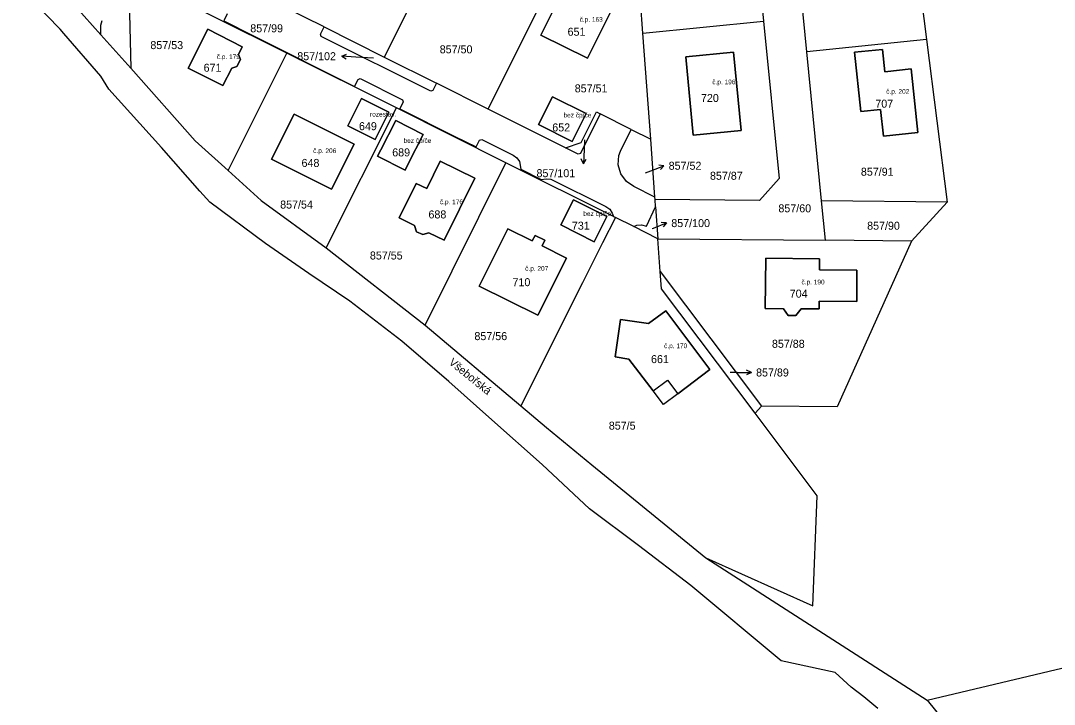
# Model space of a CAD drawing. Extents: x -887272 to -877616, y -1026687 to -1019819.
# Drawn here: x -886371.5 to -886152, y -1024532.4 to -1024387 of the extents above; entities that cross this region are included whole.
import ezdxf

# ---------------------------------------------------------------- set-up
doc = ezdxf.new("R2010")
doc.units = 0
for name, color, linetype in [('Definiční body', 7, 'Continuous'), ('Hranice parcel', 7, 'Continuous'), ('Parcelní čísla', 7, 'Continuous'), ('Polygon budovy', 7, 'Continuous'), ('Pop  PČ popisy', 7, 'Continuous'), ('Vnitřní kresba', 7, 'Continuous')]:
    doc.layers.add(name, color=color, linetype=linetype)

msp = doc.modelspace()

# ---------------------------------------------------------------- linework, layer by layer
at = {"layer": 'Hranice parcel'}
for p, q in [((-886183.54, -1024356.31), (-886179.13, -1024391.05)), ((-886204.52, -1024393.61), (-886207.95, -1024358.74)), ((-886278.64, -1024363.46), (-886294.28, -1024394.77)), ((-886272.23, -1024405.8), (-886256.6, -1024374.49)), ((-886365.01, -1024378.17), (-886354.46, -1024390.01)), ((-886307.08, -1024388.36), (-886319.32, -1024382.23)), ((-886239.34, -1024389.68), (-886239.83, -1024382.88)), ((-886239.34, -1024389.68), (-886213.7, -1024387.12)), ((-886307.08, -1024388.36), (-886294.28, -1024394.77)), ((-886354.51, -1024398.78), (-886362.33, -1024389.78)), ((-886354.46, -1024390.01), (-886348.15, -1024397.1)), ((-886237.7, -1024412.2), (-886239.34, -1024389.68)), ((-886179.13, -1024391.05), (-886204.52, -1024393.61)), ((-886179.13, -1024391.05), (-886174.74, -1024425.59)), ((-886201.39, -1024425.35), (-886204.52, -1024393.61)), ((-886327.47, -1024418.9), (-886314.97, -1024393.92)), ((-886291.71, -1024405.57), (-886314.97, -1024393.92)), ((-886294.28, -1024394.77), (-886283.2, -1024400.31)), ((-886352.76, -1024401.6), (-886354.51, -1024398.78)), ((-886272.23, -1024405.8), (-886283.2, -1024400.31)), ((-886341.64, -1024413.97), (-886352.76, -1024401.6)), ((-886306.62, -1024435.3), (-886291.71, -1024405.57)), ((-886268.45, -1024417.21), (-886291.71, -1024405.57)), ((-886255.82, -1024414.02), (-886272.23, -1024405.8)), ((-886241.84, -1024410.12), (-886248.41, -1024406.82)), ((-886241.84, -1024410.12), (-886237.7, -1024412.2)), ((-886236.81, -1024424.51), (-886237.7, -1024412.2)), ((-886333.44, -1024423.24), (-886341.64, -1024413.97)), ((-886285.57, -1024451.74), (-886268.45, -1024417.21)), ((-886245.62, -1024428.63), (-886268.45, -1024417.21)), ((-886236.77, -1024425.07), (-886236.81, -1024424.51)), ((-886236.66, -1024426.62), (-886236.77, -1024425.07)), ((-886236.66, -1024426.62), (-886236.17, -1024433.37)), ((-886174.74, -1024425.59), (-886201.39, -1024425.35)), ((-886200.57, -1024433.71), (-886201.39, -1024425.35)), ((-886174.74, -1024425.59), (-886182.28, -1024433.89)), ((-886245.62, -1024428.63), (-886245.19, -1024428.85)), ((-886241.27, -1024430.81), (-886245.19, -1024428.85)), ((-886236.17, -1024433.37), (-886241.27, -1024430.81)), ((-886310.31, -1024440.75), (-886319.49, -1024434.41)), ((-886306.62, -1024435.3), (-886285.57, -1024451.74)), ((-886235.67, -1024440.34), (-886236.17, -1024433.37)), ((-886236.17, -1024433.37), (-886200.57, -1024433.71)), ((-886182.28, -1024433.89), (-886200.57, -1024433.71)), ((-886301.62, -1024446.68), (-886310.31, -1024440.75)), ((-886235.67, -1024440.34), (-886214.13, -1024468.94)), ((-886290.56, -1024455.12), (-886301.62, -1024446.68)), ((-886285.57, -1024451.74), (-886265.29, -1024468.92)), ((-886280.6, -1024463.7), (-886290.56, -1024455.12)), ((-886271.41, -1024471.88), (-886280.6, -1024463.7)), ((-886214.13, -1024468.94), (-886215.5, -1024470.45)), ((-886260.72, -1024481.38), (-886271.41, -1024471.88)), ((-886250.66, -1024490.78), (-886260.72, -1024481.38)), ((-886240.32, -1024498.62), (-886250.66, -1024490.78)), ((-886229.14, -1024507.06), (-886240.32, -1024498.62)), ((-886226, -1024501.2), (-886178.96, -1024531.47)), ((-886210, -1024523.12), (-886229.14, -1024507.06)), ((-886198.48, -1024525.62), (-886210, -1024523.12)), ((-886195.1, -1024528.68), (-886198.48, -1024525.62)), ((-886178.96, -1024531.47), (-886171.88, -1024540.22))]:
    msp.add_line(p, q, dxfattribs=at)
for points in [[(-886217.52, -1024348.31), (-886217.13, -1024352.27), (-886213.7, -1024387.12)], [(-886245.34, -1024383.36), (-886251.15, -1024395.02), (-886261.02, -1024390.1), (-886255.2, -1024378.44), (-886245.34, -1024383.36)], [(-886362.33, -1024389.78), (-886363.1, -1024388.82), (-886371.52, -1024380.16)], [(-886314.97, -1024393.92), (-886345.74, -1024378.52), (-886348.57, -1024379.62), (-886348.15, -1024397.1)], [(-886354.46, -1024390.01), (-886354.46, -1024387.95), (-886354.24, -1024386.98)], [(-886327.64, -1024385.57), (-886328.39, -1024387.07), (-886322.23, -1024390.15), (-886300.63, -1024401), (-886299.85, -1024399.51), (-886299.39, -1024399.33), (-886290.43, -1024403.82), (-886290.28, -1024404.26), (-886290.97, -1024405.73), (-886279.3, -1024411.67), (-886274.8, -1024413.85), (-886274.06, -1024412.4), (-886273.57, -1024412.25), (-886266.94, -1024415.62), (-886266.14, -1024416.17), (-886265.55, -1024416.98), (-886265.28, -1024418.59), (-886260.98, -1024420.8), (-886259.88, -1024420.61), (-886258.89, -1024420.73), (-886247.21, -1024426.55), (-886246.38, -1024427.12), (-886245.86, -1024427.94), (-886245.62, -1024428.63)], [(-886213.7, -1024387.12), (-886210.41, -1024420.59), (-886214.57, -1024425.25), (-886236.77, -1024425.07)], [(-886178.96, -1024531.47), (-886032.7, -1024496.7), (-886031.92, -1024386.7)], [(-886325.62, -1024396.76), (-886326.69, -1024397.12), (-886328.55, -1024400.8), (-886335.92, -1024397.12), (-886331.8, -1024388.85), (-886324.44, -1024392.55), (-886325.24, -1024394.18), (-886324.86, -1024395.25), (-886325.62, -1024396.76)], [(-886283.2, -1024400.31), (-886283.98, -1024401.84), (-886284.42, -1024402.02), (-886307.69, -1024390.37), (-886307.85, -1024389.88), (-886307.08, -1024388.36)], [(-886230.26, -1024394.68), (-886220.11, -1024393.69), (-886218.47, -1024410.35), (-886228.67, -1024411.35), (-886230.26, -1024394.68)], [(-886188.48, -1024393.13), (-886187.97, -1024397.86), (-886182.34, -1024397.28), (-886180.95, -1024410.81), (-886188.27, -1024411.57), (-886188.86, -1024405.87), (-886193.06, -1024406.31), (-886194.38, -1024393.73), (-886188.48, -1024393.13)], [(-886348.15, -1024397.1), (-886334.48, -1024412.57), (-886327.47, -1024418.9)], [(-886302.04, -1024409.36), (-886299.13, -1024403.55), (-886293.32, -1024406.45), (-886296.23, -1024412.27), (-886302.04, -1024409.36)], [(-886258.53, -1024403.18), (-886251.39, -1024406.78), (-886254.36, -1024412.68), (-886261.5, -1024409.08), (-886258.53, -1024403.18)], [(-886305.48, -1024422.86), (-886318.23, -1024416.48), (-886313.43, -1024406.91), (-886300.69, -1024413.25), (-886305.48, -1024422.86)], [(-886255.82, -1024414.02), (-886252.48, -1024412.9), (-886249.24, -1024406.4), (-886248.41, -1024406.82)], [(-886248.41, -1024406.82), (-886252.64, -1024415.27), (-886253.07, -1024415.4), (-886255.82, -1024414.02)], [(-886291.85, -1024408.26), (-886286.04, -1024411.21), (-886289.21, -1024417.46), (-886289.88, -1024418.79), (-886295.7, -1024415.85), (-886295.02, -1024414.51), (-886291.85, -1024408.26)], [(-886236.81, -1024424.51), (-886241.25, -1024422.3), (-886242.85, -1024421.18), (-886244.05, -1024419.58), (-886244.6, -1024417.67), (-886244.46, -1024415.68), (-886244.14, -1024414.74), (-886241.84, -1024410.12)], [(-886286.12, -1024432.51), (-886287.41, -1024431.9), (-886287.86, -1024430.59), (-886291.1, -1024428.96), (-886287.5, -1024421.63), (-886285.26, -1024422.72), (-886282.38, -1024416.88), (-886275.06, -1024420.48), (-886281.56, -1024433.68), (-886284.8, -1024432.1), (-886286.12, -1024432.51)], [(-886327.47, -1024418.9), (-886320.47, -1024425.23), (-886306.62, -1024435.3)], [(-886319.49, -1024434.41), (-886331.34, -1024425.62), (-886333.44, -1024423.24)], [(-886249.73, -1024434), (-886256.79, -1024430.45), (-886254.06, -1024425.1), (-886247.03, -1024428.65), (-886249.73, -1024434)], [(-886241.27, -1024430.81), (-886240.65, -1024430.49), (-886239.67, -1024430.42), (-886238.6, -1024430.69), (-886236.66, -1024426.62)], [(-886245.19, -1024428.85), (-886247.91, -1024434.28), (-886252.17, -1024442.77), (-886265.29, -1024468.92)], [(-886262.87, -1024433.84), (-886262.24, -1024432.66), (-886260.17, -1024433.7), (-886260.77, -1024434.89), (-886255.59, -1024437.49), (-886261.69, -1024449.63), (-886274.16, -1024443.45), (-886268.03, -1024431.24), (-886262.87, -1024433.84)], [(-886182.28, -1024433.89), (-886198.12, -1024469.1), (-886214.13, -1024468.94)], [(-886205.74, -1024448.29), (-886206.87, -1024449.68), (-886208.47, -1024449.67), (-886209.52, -1024448.25), (-886213.35, -1024448.19), (-886213.25, -1024437.52), (-886201.83, -1024437.62), (-886201.85, -1024440), (-886193.9, -1024440.07), (-886193.94, -1024446.73), (-886201.92, -1024446.64), (-886201.92, -1024448.28), (-886205.74, -1024448.29)], [(-886215.5, -1024470.45), (-886235.4, -1024444), (-886235.67, -1024440.34)], [(-886242.31, -1024458.96), (-886245.27, -1024458.48), (-886244.14, -1024450.56), (-886238.17, -1024451.42), (-886234.47, -1024448.68), (-886225.11, -1024461.18), (-886231.94, -1024466.32), (-886235.01, -1024468.63), (-886237.19, -1024465.74), (-886242.31, -1024458.96)], [(-886265.29, -1024468.92), (-886259.85, -1024473.53), (-886250.22, -1024481.41), (-886226, -1024501.2)], [(-886226, -1024501.2), (-886203.23, -1024511.39), (-886202.3, -1024488), (-886215.5, -1024470.45)], [(-886189.42, -1024533.25), (-886192.4, -1024530.76), (-886195.1, -1024528.68)]]:
    msp.add_lwpolyline(points, dxfattribs=at)
at = {"layer": 'Polygon budovy'}
for points in [[(-886255.2, -1024378.44), (-886261.02, -1024390.1), (-886251.15, -1024395.02), (-886245.34, -1024383.36)], [(-886331.8, -1024388.85), (-886335.92, -1024397.12), (-886328.55, -1024400.8), (-886326.69, -1024397.12), (-886325.62, -1024396.76), (-886324.86, -1024395.25), (-886325.24, -1024394.18), (-886324.44, -1024392.55)], [(-886230.26, -1024394.68), (-886228.67, -1024411.35), (-886218.47, -1024410.35), (-886220.11, -1024393.69)], [(-886188.48, -1024393.13), (-886194.38, -1024393.73), (-886193.06, -1024406.31), (-886188.86, -1024405.87), (-886188.27, -1024411.57), (-886180.95, -1024410.81), (-886182.34, -1024397.28), (-886187.97, -1024397.86)], [(-886299.13, -1024403.55), (-886302.04, -1024409.36), (-886296.23, -1024412.27), (-886293.32, -1024406.45)], [(-886258.53, -1024403.18), (-886261.5, -1024409.08), (-886254.36, -1024412.68), (-886251.39, -1024406.78)], [(-886300.69, -1024413.25), (-886313.43, -1024406.91), (-886318.23, -1024416.48), (-886305.48, -1024422.86)], [(-886289.21, -1024417.46), (-886286.04, -1024411.21), (-886291.85, -1024408.26), (-886295.02, -1024414.51), (-886295.7, -1024415.85), (-886289.88, -1024418.79)], [(-886282.38, -1024416.88), (-886285.26, -1024422.72), (-886287.5, -1024421.63), (-886291.1, -1024428.96), (-886287.86, -1024430.59), (-886287.41, -1024431.9), (-886286.12, -1024432.51), (-886284.8, -1024432.1), (-886281.56, -1024433.68), (-886275.06, -1024420.48)], [(-886247.03, -1024428.65), (-886254.06, -1024425.1), (-886256.79, -1024430.45), (-886249.73, -1024434)], [(-886274.16, -1024443.45), (-886261.69, -1024449.63), (-886255.59, -1024437.49), (-886260.77, -1024434.89), (-886260.17, -1024433.7), (-886262.24, -1024432.66), (-886262.87, -1024433.84), (-886268.03, -1024431.24)], [(-886213.25, -1024437.52), (-886213.35, -1024448.19), (-886209.52, -1024448.25), (-886208.47, -1024449.67), (-886206.87, -1024449.68), (-886205.74, -1024448.29), (-886201.92, -1024448.28), (-886201.92, -1024446.64), (-886193.94, -1024446.73), (-886193.9, -1024440.07), (-886201.85, -1024440), (-886201.83, -1024437.62)], [(-886237.19, -1024465.74), (-886234.1, -1024463.43), (-886231.94, -1024466.32), (-886225.11, -1024461.18), (-886234.47, -1024448.68), (-886238.17, -1024451.42), (-886244.14, -1024450.56), (-886245.27, -1024458.48), (-886242.31, -1024458.96)]]:
    msp.add_lwpolyline(points, close=True, dxfattribs=at)
at = {"layer": 'Pop  PČ popisy'}
for p, q in [((-886303.32, -1024394.56), (-886302.29, -1024394.13)), ((-886300.33, -1024394.77), (-886303.32, -1024394.56)), ((-886303.32, -1024394.56), (-886302.36, -1024395.13)), ((-886296.59, -1024395.01), (-886300.33, -1024394.77)), ((-886251.73, -1024412.38), (-886251.82, -1024414.44)), ((-886251.82, -1024414.44), (-886251.98, -1024417.44)), ((-886251.98, -1024417.44), (-886252.43, -1024416.41)), ((-886251.98, -1024417.44), (-886251.43, -1024416.46)), ((-886237.68, -1024418.93), (-886234.88, -1024417.85)), ((-886234.88, -1024417.85), (-886235.99, -1024417.75)), ((-886234.88, -1024417.85), (-886235.63, -1024418.68)), ((-886238.79, -1024419.36), (-886237.68, -1024418.93)), ((-886237.41, -1024431.21), (-886237.13, -1024431.1)), ((-886237.13, -1024431.1), (-886234.33, -1024430.03)), ((-886234.33, -1024430.03), (-886235.44, -1024429.92)), ((-886234.33, -1024430.03), (-886235.08, -1024430.85)), ((-886219.31, -1024461.81), (-886220.79, -1024461.81)), ((-886219.31, -1024461.81), (-886216.31, -1024461.81)), ((-886216.31, -1024461.81), (-886217.31, -1024461.31)), ((-886216.31, -1024461.81), (-886217.31, -1024462.31))]:
    msp.add_line(p, q, dxfattribs=at)
at = {"layer": 'Vnitřní kresba'}
for p, q in [((-886237.19, -1024465.74), (-886234.1, -1024463.43)), ((-886234.1, -1024463.43), (-886231.94, -1024466.32))]:
    msp.add_line(p, q, dxfattribs=at)

# ---------------------------------------------------------------- texts
at = {"layer": 'Definiční body'}
for s, p in [('č.p. 163', (-886252.79, -1024387.25)), ('č.p. 179', (-886329.87, -1024395.18)), ('č.p. 196', (-886224.61, -1024400.54)), ('č.p. 202', (-886187.67, -1024402.56)), ('rozestav.', (-886297.31, -1024407.4)), ('bez čp/če', (-886256.21, -1024407.59)), ('bez čp/če', (-886290.19, -1024413)), ('č.p. 206', (-886309.39, -1024415.16)), ('č.p. 176', (-886282.47, -1024426.04)), ('bez čp/če', (-886252.01, -1024428.53)), ('č.p. 207', (-886264.36, -1024440.19)), ('č.p. 190', (-886205.66, -1024443.08)), ('č.p. 170', (-886234.85, -1024456.64))]:
    msp.add_text(s, height=1, dxfattribs=at).set_placement(p)
at = {"layer": 'Parcelní čísla'}
for s, p in [('857/99', (-886322.75, -1024389.49)), ('651', (-886255.35, -1024390.22)), ('857/53', (-886343.97, -1024393.06)), ('857/102', (-886312.77, -1024395.42)), ('857/50', (-886282.51, -1024393.96)), ('671', (-886332.66, -1024397.87)), ('857/51', (-886253.83, -1024402.26)), ('720', (-886227.02, -1024404.3)), ('707', (-886189.98, -1024405.51)), ('649', (-886299.66, -1024410.3)), ('652', (-886258.6, -1024410.56)), ('689', (-886292.6, -1024415.87)), ('648', (-886311.86, -1024418.11)), ('857/52', (-886233.88, -1024418.71)), ('857/101', (-886261.95, -1024420.29)), ('857/87', (-886225.1, -1024420.84)), ('857/91', (-886193.05, -1024419.98)), ('857/54', (-886316.4, -1024426.96)), ('857/60', (-886210.57, -1024427.76)), ('688', (-886284.9, -1024429.06)), ('731', (-886254.44, -1024431.45)), ('857/100', (-886233.32, -1024430.9)), ('857/90', (-886191.72, -1024431.46)), ('857/55', (-886297.34, -1024437.79)), ('710', (-886267.05, -1024443.46)), ('704', (-886208.16, -1024445.9)), ('857/56', (-886275.14, -1024454.93)), ('857/88', (-886211.94, -1024456.56)), ('661', (-886237.63, -1024459.82)), ('857/89', (-886215.31, -1024462.66)), ('857/5', (-886246.59, -1024473.96))]:
    msp.add_text(s, height=1.7, dxfattribs=at).set_placement(p)
at = {"layer": 'Pop  PČ popisy'}
msp.add_text('Všebořská', height=1.7, rotation=321, dxfattribs=at).set_placement((-886280.72, -1024459.91))

doc.saveas('drawing.dxf')
